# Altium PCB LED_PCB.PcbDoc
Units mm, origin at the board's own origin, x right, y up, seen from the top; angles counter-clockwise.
Board outline 99.87 x 66.87 mm, 2 copper layers (Top Layer, Bottom Layer); 110 components, 90 nets, 363 pads, 120 vias.
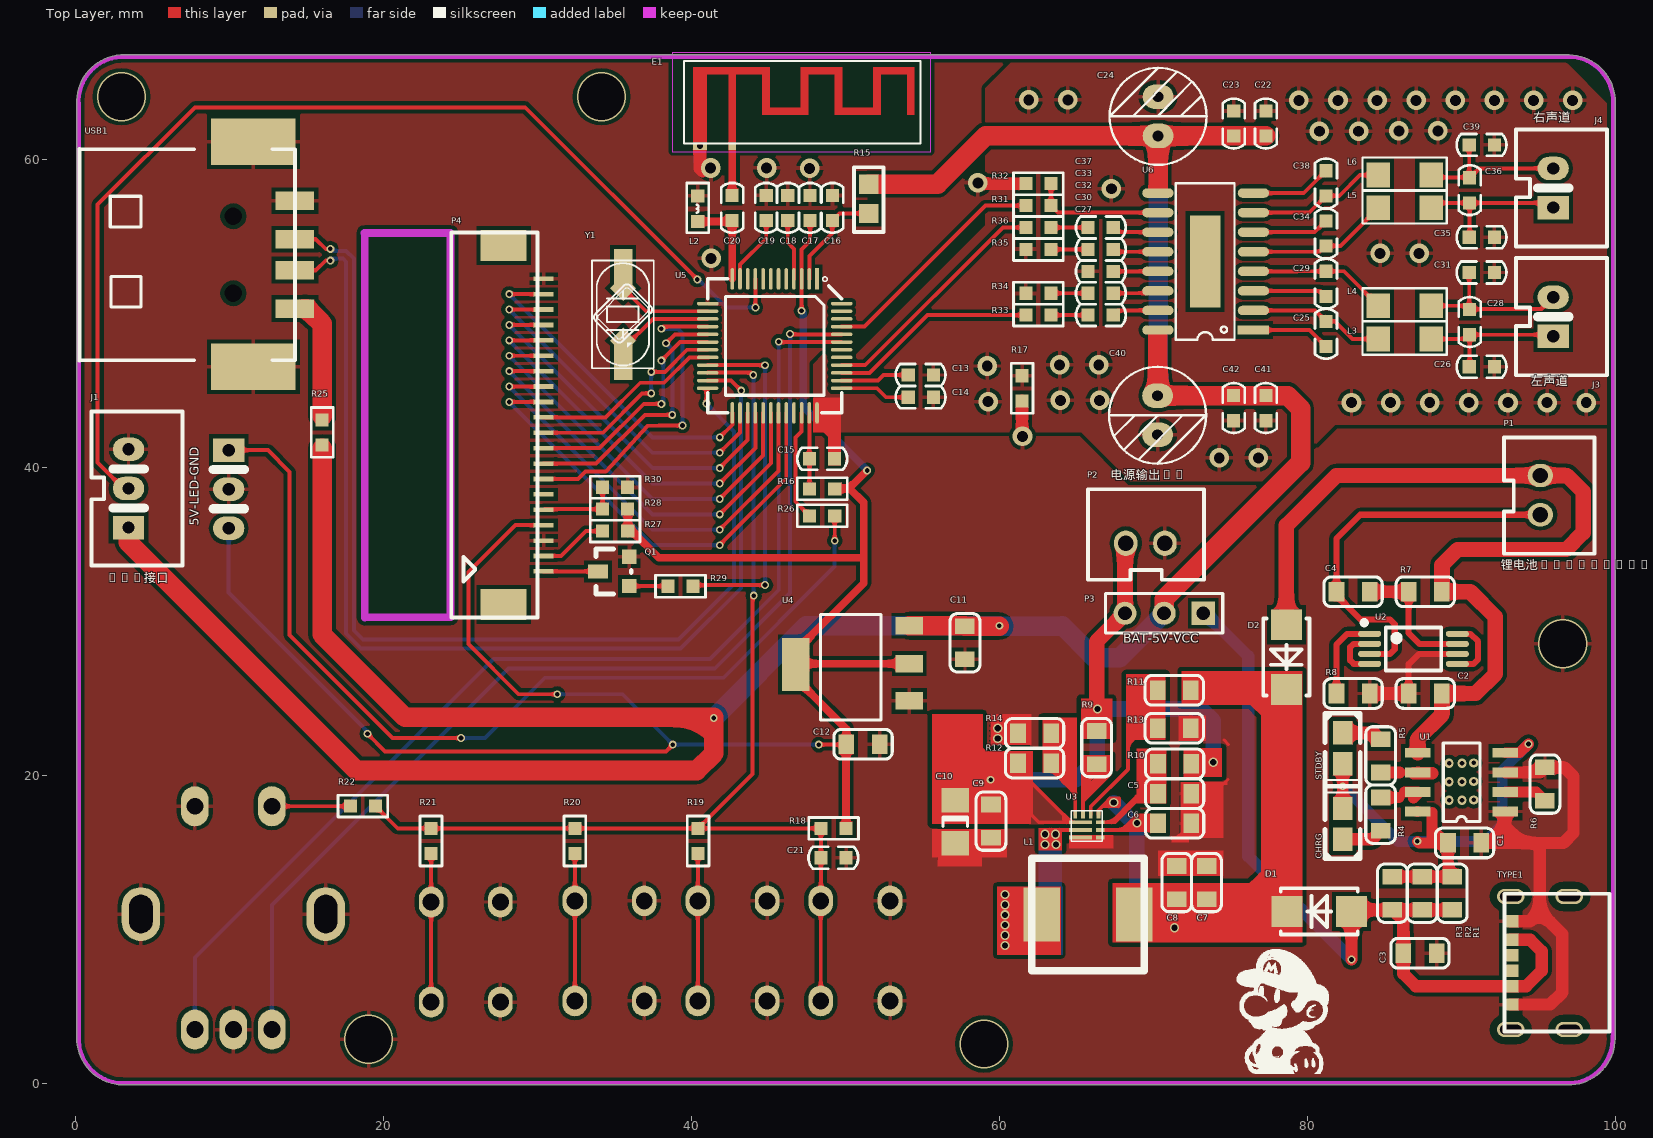
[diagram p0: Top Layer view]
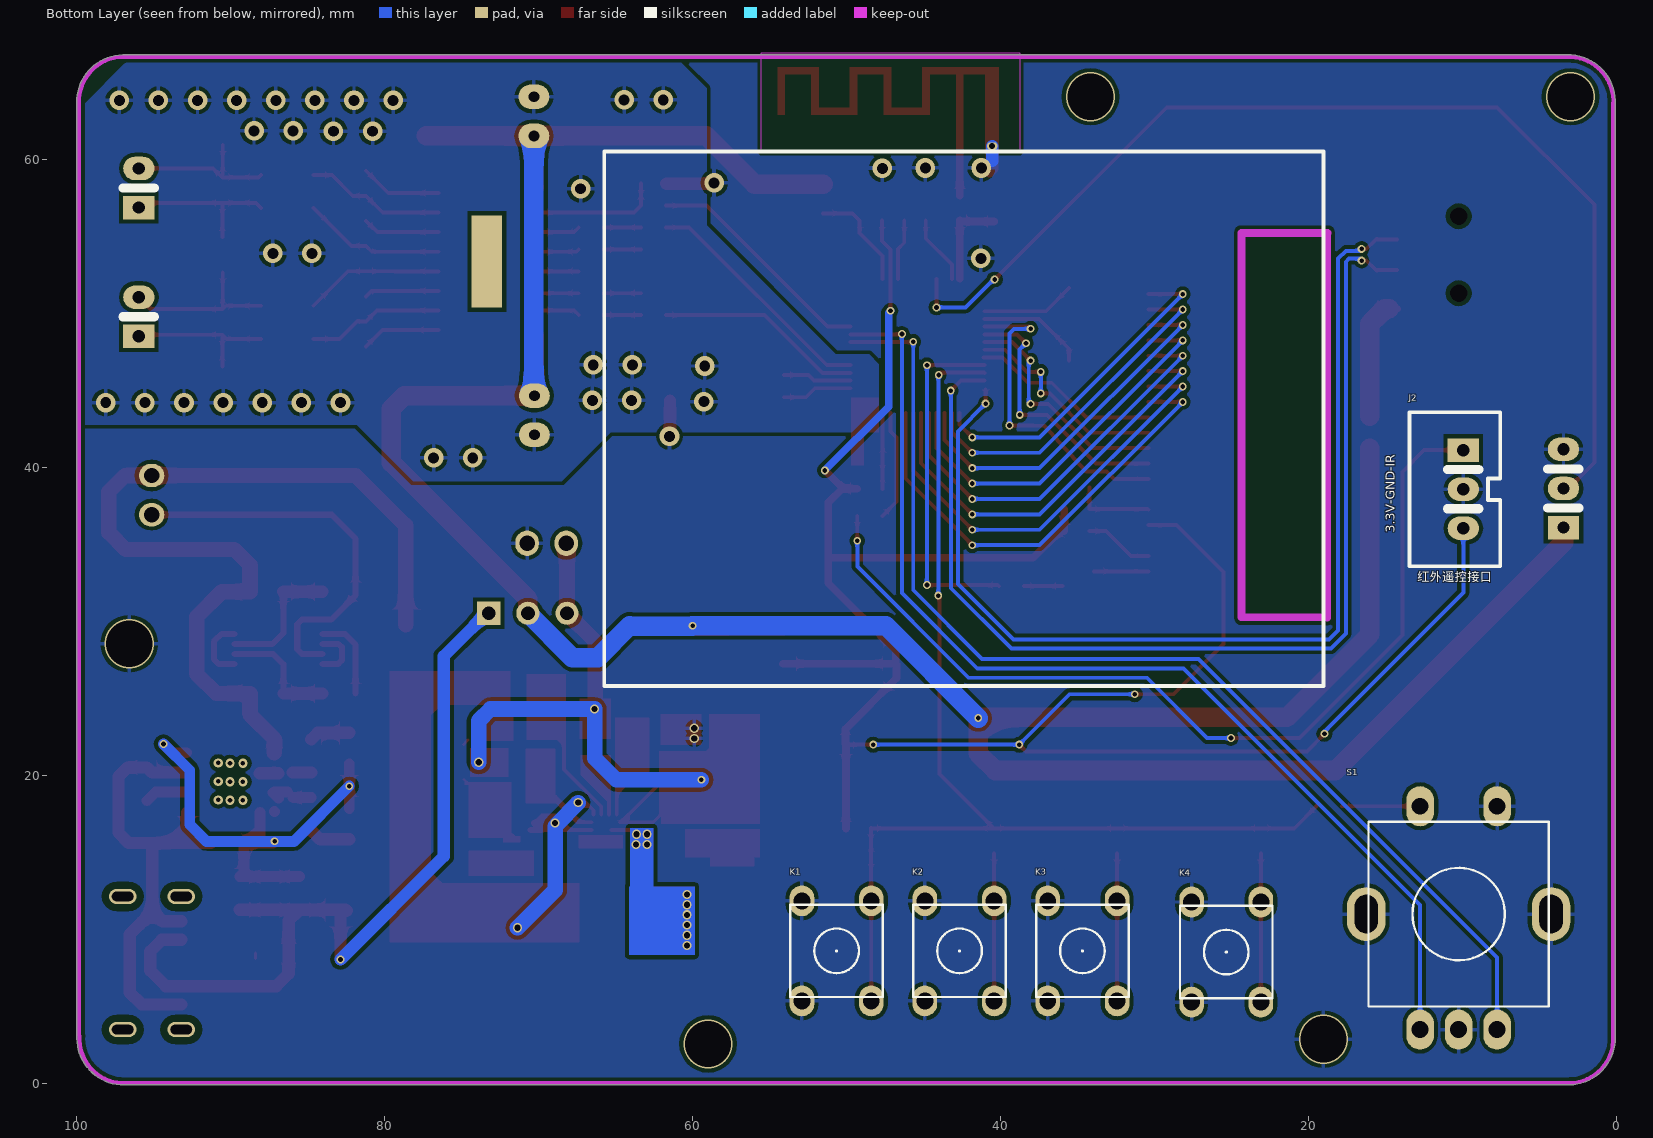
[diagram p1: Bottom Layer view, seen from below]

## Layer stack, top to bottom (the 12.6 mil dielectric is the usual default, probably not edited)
Top Solder: solder mask 0.0102, Solder Resist, Dk 3.5
Top Layer: signal copper 0.0356
Dielectric 1: dielectric 0.32, FR-4, Dk 4.8
Bottom Layer: signal copper 0.0356
Bottom Solder: solder mask 0.0102, Solder Resist, Dk 3.5

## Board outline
0.081,2.784 0.081,22.784 cw(c0.208,22.784) 0.081,22.784 0.081,63.598 cw(c3.104,63.779) 2.917,66.802 cw(c3.104,63.779) 2.918,66.802 2.917,66.802 cw(c2.926,66.675) 2.926,66.802 96.698,66.802 cw(c96.698,66.675) 96.718,66.801 cw(c96.737,66.675) 96.729,66.802 cw(c96.915,63.779) 99.938,63.965 cw(c99.811,63.957) 99.938,63.957 99.938,3.143 cw(c96.915,2.962) 99.943,2.962 cw(c96.915,2.962) 97.126,-0.059 cw(c97.104,0.066) 97.104,-0.061 3.286,-0.061 cw(c3.104,2.962) 0.081,2.776 cw(c0.208,2.784)

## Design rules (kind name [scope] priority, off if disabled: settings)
Clearance [All] p1: gap=0.254 ignorepadtopadclearanceinfootprint=TRUE
ComponentClearance [All] p1: gap=0 collisioncheckmode=3 verticalgap=0 showdistances=FALSE
DiffPairsRouting DiffPair_50omuDiffPairsRouting [InDifferentialPair ('USBDX')] p1: maxlimit=0.508 minlimit=0.254 mostfreqgap=0.254 toplayer_minwidth=0.152 toplayer_maxwidth=0.381 toplayer_prefwidth=0.254 bottomlayer_minwidth=0.152 bottomlayer_maxwidth=0.381 bottomlayer_prefwidth=0.254 maxuncoupledlength=12.7
HoleSize [All] p1: absolutevalues=TRUE maxlimit=10 minlimit=0 maxpercent=80.000 minpercent=20.000
HoleToHoleClearance [All] p1: gap=0 allowstackedmicrovias=TRUE
MatchedLengths MatchedLengths_1 [InDifferentialPair ('USBDX')] p1: tolerance=25.4 checknetsindiffpair=FALSE checkdiffpairvsdiffpair=TRUE checkxsignals=TRUE checkothers=TRUE
MatchedLengths DiffPair_50omuMatchedLengths [InDifferentialPair ('USBDX')] p2: tolerance=0.254 checknetsindiffpair=FALSE checkdiffpairvsdiffpair=TRUE checkxsignals=TRUE checkothers=TRUE
MatchedLengths [InDifferentialPair ('USBDX')] p3: tolerance=25.4 checknetsindiffpair=FALSE checkdiffpairvsdiffpair=TRUE checkxsignals=TRUE checkothers=TRUE
MinimumSolderMaskSliver [All] p1: minsoldermaskwidth=0
PolygonConnect [All] p1: connectstyle=Relief reliefconductorwidth=0.254 reliefentries=4 polygonreliefangle="90 Angle" airgapwidth=0.254
RoutingVias [All] p1: holewidth=0.711 width=1.27 viastyle="Through Hole" minholewidth=0.152 minwidth=0.254 maxholewidth=0.711 maxwidth=1.27
SilkToSilkClearance [All] p1: silktosilkclearance=0
SilkToSolderMaskClearance [IsPad] p1: minsilkscreentomaskgap=0 clearancetoexposedcopper=TRUE
SolderMaskExpansion [All] p1: expansion=0.102
Width [All] p1: maxlimit=2.54 minlimit=0.152 preferedwidth=0.254
23 further rules are at their usual default settings.

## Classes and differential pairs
component class LED原理图: C1 C2 C3 C4 C5 C6 C7 C8 C9 C10 C11 C12 CHRG D1 D2 L1 P1 P2 P3 R1 R2 R3 R4 R5 R6 R7 R8 R9 R10 R11 R12 R13 R14 STDBY TYPE1 U1 U2 U3 U4 U?
component class BLE主控原理图: C13 C14 C15 C16 C17 C18 C19 C20 C21 E1 J1 J2 K1 K2 K3 K4 L2 P4 Q1 R15 R16 R17 R18 R19 R20 R21 R22 R25 R26 R27 R28 R29 R30 S1 U5 USB1 Y1
component class 功放原理图: C22 C23 C24 C25 C26 C27 C28 C29 C30 C31 C32 C33 C34 C35 C36 C37 C38 C39 C40 C41 C42 J3 J4 L3 L4 L5 L6 R31 R32 R33 R34 R35 R36 U6
differential pair USBDX: +USBDX_P -USBDX_N

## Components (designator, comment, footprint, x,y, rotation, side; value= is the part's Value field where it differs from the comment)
C1 "Cap" 0805C 89.091,15.644 r0 top value=106
C2 "Cap" 0805C 88.699,25.347 r180 top value=106
C3 "Cap" 0805C 88.354,8.481 r180 top value=226
C4 "Cap" 0805C 81.852,31.951 r0 top value=106
C5 "Cap" 0805C 72.426,18.848 r180 top value=475
C6 "Cap" 0805C 70.269,16.918 r0 top value=105
C7 "Cap" 0805C 73.419,14.149 r270 top value=226
C8 "Cap" 0805C 71.488,14.149 r270 top value=226
C9 "Cap" 0805C 59.423,18.137 r270 top value=226
C10 "Cap2" C1206 57.112,17.019 r270 top value=100uF/10V
C11 "Cap" 0805C 57.734,27.559 r90 top value=105
C12 "Cap" 0805C 52.197,22.048 r180 top value=105
C13 "105" C0603 54.864,46.025 r0 top
C14 "105" C0603 54.864,44.577 r0 top
C15 "105" C0603 48.456,40.589 r180 top
C16 "105" C0603 49.124,56.866 r270 top
C17 "105" C0603 47.676,56.866 r270 top
C18 "105" C0603 46.228,56.866 r270 top
C19 "105" C0603 44.831,56.866 r270 top
C20 "2.7P" C0603 42.621,56.866 r270 top
C21 "NC/100pF" C0603 49.2,14.682 r0 top
C22 "104" C0603 77.272,62.357 r90 top
C23 "105" C0603 75.184,62.357 r90 top
C24 "220uF/25V" EC2.5-6.3 70.282,62.816 r90 top
C25 "105" C0603 81.174,48.692 r270 top
C26 "105" C0603 91.288,46.558 r0 top
C27 "225" C0603 66.546,49.911 r180 top
C28 "474" C0603 90.5,49.454 r270 top
C29 "105" C0603 81.174,51.943 r270 top
C30 "225" C0603 66.546,51.333 r180 top
C31 "105" C0603 91.288,52.68 r0 top
C32 "105" C0603 66.546,52.756 r180 top
C33 "225" C0603 66.546,54.178 r180 top
C34 "105" C0603 81.178,55.22 r90 top
C35 "105" C0603 91.288,54.966 r0 top
C36 "474" C0603 90.5,58.014 r270 top
C37 "225" C0603 66.546,55.601 r180 top
C38 "105" C0603 81.178,58.471 r90 top
C39 "105" C0603 91.288,60.96 r0 top
C40 "220uF/25V" EC2.5-6.3 70.231,43.411 r270 top
C41 "105" C0603 77.267,43.868 r270 top
C42 "104" C0603 75.179,43.868 r270 top
CHRG "RED" LED-0805 82.258,15.879 r90 top
D1 "SS34" LC-SMA(DO-214AC)_S2 80.734,11.199 r0 top
D2 "SS34" LC-SMA(DO-214AC)_S2 78.6,27.713 r90 top
E1 "BT_ANT" 新F天线 42.621,60.884 r0 top
J1 "LED" CON-3X2.54 3.429,38.659 r90 top
J2 "CON3" CON-3X2.54 9.931,38.608 r270 bottom
J3 "喇叭" CON-2X2.54 95.921,48.539 r90 top
J4 "喇叭" CON-2X2.54 95.921,56.896 r90 top
K1 "" KEY 50.622,8.636 r270 bottom
K2 "" KEY 42.641,8.636 r270 bottom
K3 "" KEY 34.661,8.636 r270 bottom
K4 "" KEY 25.324,8.56 r270 bottom
L1 "Inductor" 电感SMD 65.72,10.999 r180 top value=1R5
L2 "NC" L0603 40.386,56.818 r270 top
L3 "100R/10uH" R1206 86.284,48.362 r180 top
L4 "100R/10uH" R1206 86.284,50.521 r180 top
L5 "100R/10uH" R1206 86.284,56.871 r180 top
L6 "100R/10uH" R1206 86.284,59.004 r180 top
P1 "Header 2" XH2.54-2 95.092,39.498 r90 top
P2 "Header 2" XH2.54-2 68.174,35.103 r180 top
P3 "Header 3" HDR1X3 73.203,30.556 r180 top
P4 "串口彩屏" FFC-P20-1MM 29.083,42.774 r90 top
Q1 "S9014" SOT23 34.925,33.325 r90 top
R1 "Res2" 0805R 89.37,11.3 r90 top value=1R
R2 "Res2" 0805R 87.414,11.3 r90 top value=1R
R3 "Res2" 0805R 85.484,11.3 r90 top value=1R
R4 "Res2" 0805R 84.722,16.431 r90 top value=2K
R5 "Res2" 0805R 84.722,22.375 r270 top value=10K
R6 "Res2" 0805R 95.39,20.546 r270 top value=2K
R7 "Res2" 0805R 88.699,31.951 r180 top value=100R
R8 "Res2" 0805R 81.852,25.347 r0 top value=1K
R9 "Res2" 0805R 66.281,20.753 r90 top value=100K
R10 "Res2" 0805R 70.269,20.778 r0 top value=1K
R11 "Res2" 0805R 72.403,25.554 r180 top value=300K
R12 "Res2" 0805R 63.332,20.829 r180 top value=470K
R13 "Res2" 0805R 72.403,23.09 r180 top value=50K
R14 "Res2" 0805R 61.176,22.76 r0 top value="148K4      268K"
R15 "4R7" R0805 51.486,57.455 r270 top
R16 "4R7" R0603 48.463,38.633 r0 top
R17 "0R" R0603 61.443,45.161 r90 top
R18 "22K" R0603 49.2,16.586 r0 top
R19 "3K" R0603 40.411,15.773 r270 top
R20 "6.2K" R0603 32.41,15.773 r270 top
R21 "9.1K" R0603 23.063,15.773 r270 top
R22 "33K" R0603 18.646,18.034 r180 top
R25 "2R7" R0603 16.002,42.291 r90 top
R26 "1K" R0603 48.463,36.881 r0 top
R27 "0R" R0603 35.029,35.89 r180 top
R28 "3K" R0603 35.021,37.313 r0 top
R29 "10K" R0603 39.268,32.309 r180 top
R30 "10K" R0603 35.021,38.735 r0 top
R31 "10K" R0603 62.505,57.023 r180 top
R32 "10K" R0603 62.505,58.445 r180 top
R33 "1K" R0603 62.505,49.909 r180 top
R34 "1K" R0603 62.505,51.331 r180 top
R35 "1K" R0603 62.505,54.176 r180 top
R36 "1K" R0603 62.505,55.598 r180 top
S1 "编码器" BMQ+PUSH 10.236,11.024 r180 bottom
STDBY "GREEN" LED-0805 82.258,22.787 r270 top
TYPE1 "TYPE-CF-6P-RAT-L6.8W" TYPE-CF-6P-RAT-L6.8W 96.139,7.849 r90 top
U1 "TC4056A" SOP-8 92.824,17.682 r180 top
U2 "DW03D" LC-TSSOP-8_3x4.4x065P 86.855,28.242 r270 top
U3 "SY7065" QFN2*2-10 65.646,16.74 r0 top
U4 "AMS1117-3.3" SOT-233 54.111,24.868 r180 top
U5 "AC6951C" LQFP48 45.39,47.904 r270 top locked
U6 "CS8676" SOP16-EP 76.759,48.946 r180 top
USB1 "USB" USBSMT 10.236,56.331 r270 top
Y1 "HS-24M" JZ 35.535,49.962 r0 top locked

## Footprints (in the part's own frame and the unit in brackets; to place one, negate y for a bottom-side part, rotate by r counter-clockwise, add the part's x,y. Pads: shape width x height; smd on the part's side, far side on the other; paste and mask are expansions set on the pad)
0805C [mil]
  rect 40x50 smd: 1(0,0) 2(85,0)
  silkscreen extent -32,-38 117,38, body extent 3,-25 82,25, height 30
0805R [mil]
  rect 40x50 smd: 1(0,0) 2(85,0)
  silkscreen extent -32,-38 117,38, body extent 3,-25 82,25, height 30
BMQ+PUSH [mm]
  oval 1.8x2.6 hole 1.1: 1(-2.5,-7.5) 2(0,-7.5) 3(2.5,-7.5) 4(-2.5,7) 5(2.5,7)
  oval 2.5x3.5 hole 1.5 slot 2.5 at 90 deg: 6(-6,0) 7(6,0)
  silkscreen extent -5.85,-6 5.85,6
C0603 [mm]
  rect 0.85x0.85 smd: 1(-0.815,0) 2(0.815,0)
  silkscreen extent -1.63,-0.71 1.61,0.71
C1206 [mm] "Chip Capacitor; Body 3.2 x 1.6 mm (LxW typ)"
  rect 1.6x1.8 smd: 1(-1.4,0) 2(1.4,0)
  silkscreen extent -0.3,-0.8 0.3,0.8
CON-2X2.54 [mil]
  rect 60x80 hole 31.5: 1(0,0)
  oval 60x80 hole 31.5: 2(100,0)
  silkscreen extent -100,-138 200,94
CON-3X2.54 [mil]
  rect 60x80 hole 31.5: 1(-100,0)
  oval 60x80 hole 31.5: 2(0,0) 3(100,0)
  silkscreen extent -197,-138 197,94
EC2.5-6.3 [mm]
  oval 1.6x2 hole 0.7: 1(-1.27,0.01) 2(1.27,0.01)
  silkscreen extent -3.15,-3.14 3.15,3.16
FFC-P20-1MM [mm]
  rect 0.3x1.3 smd: 1(-9.5,-1.3) 2(-8.5,-1.3) 3(-7.5,-1.3) 4(-6.5,-1.3) 5(-5.5,-1.3) 6(-4.5,-1.3) 7(-3.5,-1.3) 8(-2.5,-1.3) 9(-1.5,-1.3) 10(-0.5,-1.3) 11(0.5,-1.3) 12(1.5,-1.3) 13(2.5,-1.3) 14(3.5,-1.3) 15(4.5,-1.3) 16(5.5,-1.3) 17(6.5,-1.3) 18(7.5,-1.3) 19(8.5,-1.3) 20(9.5,-1.3)
  rect 2x3 smd: 21(11.651,1.3) 22(-11.651,1.3)
  silkscreen extent -12.5,-0.9 12.5,4.7
HDR1X3 [mm] "Connector; Header; 3 Position"
  rect 1.5x1.5 hole 0.9: 1(0,0)
  round 1.5 hole 0.9: 2(2.54,0) 3(5.08,0)
  silkscreen extent -1.27,-1.27 6.35,1.27
JZ [mm]
  rect 1.2x2.5 smd: 1(0,-3) 2(0,3)
  rect 1.2x1.2 smd rot 45: 1(0,-1.7) 2(0,1.7)
  rect 1.2x1.2 on Top Overlay rot 45: 3(1.7,0) 4(-1.7,0)
  silkscreen extent -2.01,-3.5 1.99,3.5
KEY [mm]
  oval 2x1.6 hole 1.1: 1(-3.25,2.25) 1(3.25,2.25) 2(-3.25,-2.25) 2(3.25,-2.25)
  silkscreen extent -3,-3 3,3
L0603 [mm]
  rect 0.85x0.85 smd: 1(-0.83,0) 2(0.83,0)
  silkscreen extent -1.68,-0.71 1.56,0.71
LC-SMA(DO-214AC)_S2 [mm]
  rect 2x2 smd: 1(2.1,0) 2(-2.1,0)
  silkscreen extent -2.5,-1.5 2.5,1.5
LC-TSSOP-8_3x4.4x065P [mm]
  oval 0.4x1.5 smd mask+0.051: 1(-0.975,-2.85) 2(-0.325,-2.85) 3(0.325,-2.85) 4(0.975,-2.85) 5(0.975,2.85) 6(0.325,2.85) 7(-0.325,2.85) 8(-0.975,2.85)
  silkscreen extent -1.85,-3.35 1.4,1.8
LED-0805 [mil]
  rect 60x50 smd: 1(0,0) 2(78.74,0)
  silkscreen extent -50,-45 136,45
LQFP48 [mm]
  rect 1.4x0.23 smd: 1(-4.357,2.739)
  oval 1.4x0.23 smd: 2(-4.357,2.239) 3(-4.357,1.739) 4(-4.357,1.239) 5(-4.357,0.739) 6(-4.357,0.239) 7(-4.357,-0.261) 8(-4.357,-0.761) 9(-4.357,-1.261) 10(-4.357,-1.761) 11(-4.357,-2.261) 12(-4.357,-2.761) 25(4.343,-2.761) 26(4.343,-2.261) 27(4.343,-1.761) 28(4.343,-1.261) 29(4.343,-0.761) 30(4.343,-0.261) 31(4.343,0.239) 32(4.343,0.739) 33(4.343,1.239) 34(4.343,1.739) 35(4.343,2.239) 36(4.343,2.739)
  oval 0.23x1.4 smd: 13(-2.757,-4.361) 14(-2.257,-4.361) 15(-1.757,-4.361) 16(-1.257,-4.361) 17(-0.757,-4.361) 18(-0.257,-4.361) 19(0.243,-4.361) 20(0.743,-4.361) 21(1.243,-4.361) 22(1.743,-4.361) 23(2.243,-4.361) 24(2.743,-4.361) 37(2.743,4.339) 38(2.243,4.339) 39(1.743,4.339) 40(1.243,4.339) 41(0.743,4.339) 42(0.243,4.339) 43(-0.257,4.339) 44(-0.757,4.339) 45(-1.257,4.339) 46(-1.757,4.339) 47(-2.257,4.339) 48(-2.757,4.339)
  silkscreen extent -4.49,-4.36 4.34,4.34
QFN2*2-10 [mm]
  rect 1.5x0.25 smd: 1(-0.4,0.25) 2(-0.4,-0.25) 3(-0.4,-0.75)
  rect 0.55x0.25 smd mask+0.102: 4(0.875,-0.75)
  rect 0.55x0.25 smd: 5(0.875,-0.25) 6(0.875,0.25)
  rect 0.25x0.5 smd: 7(0.75,0.75) 8(0.25,0.75) 9(-0.25,0.75) 10(-0.75,0.75)
  silkscreen extent -1,-1 1,1, body extent -1.47,-1 1.01,1.01, height 63.5
R0603 [mm]
  rect 0.85x0.85 smd: 1(-0.815,0) 2(0.815,0)
  silkscreen extent -1.62,-0.71 1.62,0.71
R0805 [mm]
  rect 1.25x1.25 smd: 1(-0.96,0.007) 2(0.94,0.007)
  silkscreen extent -2.06,-0.95 2.16,0.96
R1206 [mm]
  rect 1.52x1.6 smd: 1(-1.71,0) 2(1.71,0)
  silkscreen extent -2.73,-1.14 2.74,1.02
SOP16-EP [mm]
  rect 2x6 all layers, no hole: 0(3.429,-4.445)
  rect 2.032x0.61 smd: 1(0.3,0)
  oval 2.032x0.61 smd: 2(0.3,-1.27) 3(0.3,-2.54) 4(0.3,-3.81) 5(0.3,-5.08) 6(0.3,-6.35) 7(0.3,-7.62) 8(0.3,-8.89) 9(6.5,-8.89) 10(6.5,-7.62) 11(6.5,-6.35) 12(6.5,-5.08) 13(6.5,-3.81) 14(6.5,-2.54) 15(6.5,-1.27) 16(6.5,0)
  silkscreen extent 1.52,-9.53 5.33,0.64
SOP-8 [mil]
  rect 65x25 smd: 1(0,0) 2(0,-50) 3(0,-100) 4(0,-150) 5(224.41,-150) 6(224.41,-100) 7(224.41,-50) 8(224.41,0)
  silkscreen extent 65,-175 159,25
SOT23 [mil]
  rect 36x36 smd: 1(-39.7,-40) 2(35.3,-40)
  rect 36x50 smd: 3(-2.2,40)
  silkscreen extent -60,-45 55,45
SOT-233 [mil]
  rect 70x45 smd: 1(0,0) 2(0,-95.04) 3(0,-192)
  rect 70x135 smd: 4(290.35,-92.95)
  silkscreen extent 72,-221 227,49
TYPE-CF-6P-RAT-L6.8W [mm]
  oval 1x1.8 hole 1.4 slot 0.6 at 0 deg unplated: 0(-4.32,-0.829) 0(-4.32,2.971) 0(4.32,-0.829) 0(4.32,2.971)
  rect 0.8x1 smd: 1(-2.7,2.971) 2(-1.5,2.971) 3(-0.5,2.971) 4(0.5,2.971) 5(1.5,2.971) 6(2.7,2.971)
  silkscreen extent -4.44,-3.43 4.49,3.37, body extent -4.44,-3.98 4.5,3.92, height 1.61
USBSMT [mm]
  rect 1.2x2.5 smd: 1(-1,4) 2(1.5,4) 3(3.5,4) 4(6,4)
  rect 3x5.5 smd: 5(-4.837,1.3) 6(9.773,1.3)
  round 0 hole 1.15: 7(5,0) 8(0,0)
  silkscreen extent -4.36,-10 9.36,4
XH2.54-2 [mil]
  oval 60x65 hole 39.37: 1(0,0) 2(-100.1,0)
  silkscreen extent -200,-138 97,93, body extent -198,-142 98,94, height 276
新F天线 [mm]
  rect 0.5x0.5 smd mask+0.003: 1(0,0)
  rect 0.5x0.5 on Top Solder mask+0.003: 1(0,0)
  rect 0.9x0.5 smd mask+0.003: 2(-2.1,0)
  oval 0.7x0.5 hole 0.4 mask+0.01: 2(-2.1,0)
  rect 0.9x0.5 on Top Solder: 2(-2.1,0)
  Top Layer region: 9.151,4.65 11.851,4.65 11.851,5.15 9.151,5.15
  Top Layer region: 6.651,2.01 9.651,2.01 9.651,2.51 6.651,2.51
  Top Layer region: 4.451,4.65 7.151,4.65 7.151,5.15 4.451,5.15
  Top Layer region: 4.451,2.01 4.951,2.01 4.951,5.15 4.451,5.15
  Top Layer region: 1.951,2.01 2.451,2.01 2.451,5.15 1.951,5.15
  Top Layer region: -0.247,-0.25 0.253,-0.25 0.253,5.15 -0.247,5.15
  Top Layer region: -2.549,-0.25 -1.65,-0.25 -1.65,5.15 -2.549,5.15
  Top Layer region: -2.549,4.65 2.451,4.65 2.451,5.15 -2.549,5.15
  Top Layer region: 1.951,2.01 4.951,2.01 4.951,2.51 1.951,2.51
  Top Layer region: 6.651,2.01 7.151,2.01 7.151,5.15 6.651,5.15
  Top Layer region: 9.151,2.01 9.651,2.01 9.651,5.15 9.151,5.15
  Top Layer region: 11.351,2.01 11.851,2.01 11.851,5.15 11.351,5.15
  silkscreen extent -3.13,0.18 12.22,5.53
电感SMD [mm]
  rect 2.35x3.5 smd: 1(-3,0) 2(3,0)
  silkscreen extent -3.65,-3.65 3.65,3.65

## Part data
C1 C2 C3 C4 C5 C6 C7 C8 C9 C10 C11 C12: "Capacitor"
C13 C14 C15 C16 C17 C18 C19 C20 C21 C22 C23 C25 C26 C27 C28 C29 C30 C31 C32 C33 C34 C35 C36 C37 C38 C39 C41 C42: library part CAP-0603
C24 C40: library part +CAP
CHRG STDBY: library part LED0, "Typical INFRARED GaAs LED"
D1 D2: library part Diode, "Default Diode"
J1: library part CON3, "Connector"
J2: "Connector"
J3 J4: library part CON2, "Connector"
K1 K2 K3 K4: library part Key
L2 L3 L4 L5 L6: library part L
P1 P2: "Header, 2-Pin"
P3: "Header, 3-Pin"
P4: library part LCD-20P
Q1: library part NPN
R1 R2 R3 R4 R5 R6 R7 R8 R9 R10 R11 R12 R13 R14: "Resistor"
R15 R17 R18 R19 R20 R21 R22 R26 R27 R28 R29 R30 R31 R32 R33 R34 R35 R36: library part RES-0603
R16 R25: library part RES
S1: library part CON7, "Connector"
Y1: library part CRYSTAL

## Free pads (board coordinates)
  rect 2.35x4 on Top Solder: 0(89.98,19.587)
  rect 2.35x4 on Bottom Solder: 1(89.903,19.562)

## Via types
v1: diameter 0.508, hole 0.305, Top Layer to Bottom Layer, 47 vias
v2: diameter 1.27, hole 0.711, Top Layer to Bottom Layer, 38 vias
v3: diameter 0.6, hole 0.4, Top Layer to Bottom Layer, 17 vias
v4: diameter 0.6, hole 0.3, Top Layer to Bottom Layer, 8 vias
v5: diameter 3.2, hole 3, Top Layer to Bottom Layer, 5 vias
v6: diameter 0.5, hole 0.3, Top Layer to Bottom Layer, 4 vias
v7: diameter 0.6/0.6 (per signal layer), hole 0.3, Top Layer to Bottom Layer, 1 vias

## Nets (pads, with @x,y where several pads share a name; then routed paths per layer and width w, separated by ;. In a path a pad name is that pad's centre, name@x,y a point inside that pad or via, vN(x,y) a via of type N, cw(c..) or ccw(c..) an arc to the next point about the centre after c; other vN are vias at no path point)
5V: C11.2 C22.1 C23.1 C24.1 C40.1 C41.1 C42.1 J1.1 P3.2 R15.1 R25.1 U4.3 U6.9 U6.16 | length 207
  Top Layer w0.254: C40.1 70.243,44.683 C40.1@70.259,44.698 ; U6.9 70.259,58.217 ; C22.1@77.267,61.546 C22.1
  Top Layer w1.27: J1.1 3.429,35.154 18.237,20.345 40.31,20.345 41.427,21.463 41.427,22.787 ; R25.1@16.002,41.274 16.002,29.185 21.387,23.8 40.335,23.8 ; R15.1 55.951,58.415 59.083,61.546 C24.1 ; U4.3 57.708,29.745 C11.2 v1@59.969,29.718 ; C40.1@70.243,44.683 C41.1 78.685,44.683 79.527,43.84 79.527,40.335 70.663,31.471 P3.2 ; C40.1@70.259,44.698 70.259,48.565 ; 70.259,58.217 70.272,58.23 C24.1 ; C22.1@77.267,61.546 C24.1 ; 40.335,23.8 41.427,23.8 v1(41.427,23.749) 41.427,22.787 ; 40.335,23.8 41.348,22.787 41.427,22.787
  Bottom Layer w1.27: v1(41.427,23.749) 47.422,29.743 v1(59.969,29.743) v1@59.995,29.743 ; v1@59.995,29.718 64.031,29.718 64.058,29.745 66.142,27.661 67.767,27.661 P3.2 ; C40.1 70.272,44.711 C24.1
+3.3V: C12.2 C17.2 J2.3 P4.4 R16.2 R18.2 R27.1 R28.2 U4.2 U4.4 U5.3 | length 146.9
  Top Layer w0.254: v1(18.948,22.733) 20.091,21.59 38.329,21.59 v1(38.764,22.025) ; P4.4 28.552,36.274 25.502,33.223 25.502,28.55 28.753,25.298 v1(31.267,25.298) ; v1(47.117,50.19) 47.129,50.202 U5.3 47.129,54.164 47.676,54.712 C17.2 ; v1(48.238,22.025) C12.2@50.015,22.025
  Top Layer w0.5: R28.2 35.844,37.305 R27.1 36.119,35.89 37.846,34.163 51.13,34.163 51.156,34.188 ; R16.2 50.19,38.633 ; R18.2 50.015,22.025 C12.2 50.038,23.038 46.736,26.34 U4.4 U4.4@46.789,27.282 ; v1(51.384,39.827) 50.19,38.633 ; U4.2 U4.4@46.789,27.282 ; U4.4@46.789,27.282 46.789,28.145 51.156,32.512 51.156,34.188 ; 50.19,38.633 50.267,38.633 51.156,37.744 51.156,34.188
  Bottom Layer w0.254: J2.3 9.931,31.902 18.948,22.885 v1(18.948,22.733) ; v1(31.267,25.298) 35.491,25.298 v1(38.764,22.025) v1(48.238,22.025)
  Bottom Layer w0.5: v1(47.117,50.19) 47.244,50.063 47.244,43.967 v1(51.384,39.827)
/CS: P4.7 U5.16 | length 21.2
  Top Layer w0.254: P4.7 32.619,39.274 33.096,39.751 34.414,39.751 37.11,42.705 37.978,42.745 ; 37.873,42.74 39.387,42.74 v1(39.395,42.748) ; v1(38.024,49.022) 38.164,49.162 U5.16
  Bottom Layer w0.254: v1(38.024,49.022) 39.091,49.022 39.395,48.717 v1(39.395,42.748)
/RSTB: P4.8 U5.17 | length 17.4
  Top Layer w0.254: P4.8 33.792,40.274 36.953,43.435 v1(38.735,43.435) ; v1(38.329,48.082) 38.908,48.662 U5.17
  Bottom Layer w0.254: v1(38.329,48.082) 38.735,47.676 v1(38.735,43.435)
AD_KEY: C21.1 K1.1 R18.1 R19.1 R20.1 R21.1 R22.1 U5.22 | length 75.2
  Top Layer w0.254: R22.1 20.906,16.588 R21.1 R20.1 R19.1 ; U5.22 41.044,46.177 43.84,46.177 v1(43.993,46.025) ; v1(44.018,31.699) 43.942,31.699 43.942,20.119 R19.1 ; K1.1@48.372,5.386 48.372,12.204 K1.1@48.385,12.217 ; K1.1@48.372,11.886 48.385,11.899 K1.1@48.385,12.217 ; R18.1@48.385,16.612 R18.1 ; R19.1 40.414,16.586 R18.1 ; K1.1@48.385,12.217 C21.1 R18.1
  Bottom Layer w0.254: v1(43.993,46.025) 43.993,46.05 44.018,46.076 v1(44.018,31.699)
AGND: C13.2 C14.2 C15.1 C22.2 C23.2 C24.2 C26.2 C31.2 C32.2 C35.2 C39.2 C40.2 C41.2 C42.2 R17.2 R34.2 R35.2 U5.36 | length 0.6
  Top Layer w0.254: 48.539,42.545 48.539,42.494 48.895,42.139 ; 49.271,42.794 49.301,42.824
  other v2: 74.244,40.64 76.784,40.64 82.829,44.235 85.369,44.235 87.909,44.235 90.449,44.235 92.989,44.235 95.529,44.235 98.069,44.235 59.233,44.298 63.932,44.374 66.472,44.374 59.182,46.609 63.881,46.685 66.421,46.685 84.684,53.924 87.224,53.924 67.234,58.115 80.747,61.849 83.287,61.849 85.903,61.874 88.443,61.874 79.411,63.856 81.951,63.856 84.491,63.856 87.031,63.856 89.571,63.856 92.111,63.856 94.651,63.856 97.191,63.856 61.874,63.881 64.414,63.881
BAT+: C2.1 D2.1 P1.1 R7.1 U1.5 | length 58.3
  Top Layer w1: D2.1 78.6,36.257 81.841,39.498 P1.1 96.822,39.498 97.866,38.454 97.866,35.787 96.774,34.695 89.713,34.695 88.699,33.682 R7.1 90.538,31.951 92.164,30.325 92.164,26.617 90.894,25.347 C2.1 88.699,23.965 87.124,22.39 U1.5
BL_A: P4.2 R27.2 | length 4.5
  Top Layer w0.254: P4.2 31.505,34.274 33.122,35.89 R27.2
BL_K: P4.1 Q1.3 | length 3.5
  Top Layer w0.254: P4.1 Q1.3@33.904,33.274
BL_LIGHT: R29.1 U5.21 | length 22.7
  Top Layer w0.254: R29.1 40.16,32.385 v1(44.755,32.385) ; U5.21 v1(44.757,46.662)
  Bottom Layer w0.254: v1(44.755,32.385) 44.755,32.61 44.757,32.612 v1(44.757,46.662)
BT_ANT: C20.1 E1.1@42.621,60.884 | length 3.2
  Top Layer w0.254: E1.1@42.621,60.858 E1.1@42.647,60.884
  Top Layer w0.5: C20.1 E1.1@42.621,60.858
BT_RF: C20.2 L2.2 U5.12 | length 6.1
  Top Layer w0.254: C20.2@42.558,55.988 C20.2 ; U5.12@42.621,52.269 U5.12
  Top Layer w0.5: L2.2 C20.2@42.558,55.988 ; U5.12@42.621,52.269 C20.2
BTAVDD: C19.2 U5.11 | length 4.5
  Top Layer w0.254: U5.11 43.129,53.187 44.831,54.889 C19.2
CTRL: R31.1 R32.1 U6.10 | length 8.6
  Top Layer w0.254: R32.1 R31.1 63.777,56.566 U6.10
DACL: R33.2 U5.39 | length 13.5
  Top Layer w0.254: U5.39 51.547,46.162 55.293,49.909 R33.2
DACR: R36.2 U5.40 | length 15.7
  Top Layer w0.254: U5.40 51.259,46.662 60.196,55.598 R36.2
DACVDD: C13.1 U5.38 | length 4.5
  Top Layer w0.254: U5.38 52.088,45.662 52.451,46.025 C13.1
DB0: P4.19 U5.25 | length 21.7
  Top Layer w0.254: v1(28.143,51.274) P4.19 ; v1(41.808,41.976) 42.629,42.796 U5.25
  Bottom Layer w0.254: v1(28.143,51.274) 37.441,41.976 v1(41.808,41.976)
DB1: P4.18 U5.26 | length 22.9
  Top Layer w0.254: v1(28.143,50.274) P4.18 ; v1(41.808,40.976) 43.129,42.296 U5.26
  Bottom Layer w0.254: v1(28.143,50.274) 37.441,40.976 v1(41.808,40.976)
DB2: P4.17 U5.27 | length 24.1
  Top Layer w0.254: v1(28.143,49.274) P4.17 ; v1(41.808,39.976) 43.629,41.796 U5.27
  Bottom Layer w0.254: v1(28.143,49.274) 37.441,39.976 v1(41.808,39.976)
DB3: P4.16 U5.28 | length 25.3
  Top Layer w0.254: v1(28.143,48.274) P4.16 ; v1(41.808,38.976) 44.129,41.296 U5.28
  Bottom Layer w0.254: v1(28.143,48.274) 37.441,38.976 v1(41.808,38.976)
DB4: P4.15 U5.29 | length 26.5
  Top Layer w0.254: v1(28.143,47.274) P4.15 ; v1(41.808,37.976) 44.629,40.796 U5.29
  Bottom Layer w0.254: v1(28.143,47.274) 37.441,37.976 v1(41.808,37.976)
DB5: P4.14 U5.30 | length 27.7
  Top Layer w0.254: v1(28.143,46.274) P4.14 ; v1(41.808,36.976) 45.129,40.296 U5.30
  Bottom Layer w0.254: v1(28.143,46.274) 37.441,36.976 v1(41.808,36.976)
DB6: P4.13 U5.31 | length 28.9
  Top Layer w0.254: v1(28.143,45.274) P4.13 ; v1(41.808,35.976) 45.629,39.796 U5.31
  Bottom Layer w0.254: v1(28.143,45.274) 37.441,35.976 v1(41.808,35.976)
DB7: P4.12 U5.32 | length 30.1
  Top Layer w0.254: v1(28.143,44.274) P4.12 ; v1(41.808,34.976) 46.129,39.296 U5.32
  Bottom Layer w0.254: v1(28.143,44.274) 37.441,34.976 v1(41.808,34.976)
GND: C1.2 C2.2 C3.1 C5.1 C6.2 C7.1 C8.1 C9.2 C10.2 C11.1 C12.1 C16.1 C17.1 C18.1 C19.1 C21.2 E1.2@40.521,60.884 J1.3 J2.2 K1.2 K2.2 K3.2 K4.2 L2.1 P2.2 P4.3 P4.20 Q1.2 R6.1 R8.2 R13.1 R14.1 R17.1 R30.2 R32.2 S1.2 S1.5 S1.6 S1.7 TYPE1.1 TYPE1.6 U1.1 U1.3 U2.6 U3.3 U3.4 U4.1 U5.13 USB1.1 USB1.5 USB1.6 | length 54.3
  Top Layer w0.2: 71.514,16.029 71.819,16.308 ; 74.511,19.483 74.816,19.762 ; 74.562,22.328 74.841,22.023 ; C3.1@88.354,8.151 C3.1
  Top Layer w0.4: C2.2 86.54,27.241 87.216,27.917 U2.6
  Top Layer w0.8: E1.2@40.521,60.884 40.521,59.431 v2@40.694,59.258 ; v2(58.572,58.496) 58.623,58.445 R32.2 ; R17.1 61.443,42.062 v2(61.468,42.037) ; R8.2 86.515,25.347 85.753,25.347 ; C1.2 91.783,15.644 ; 92.774,16.609 U1.1@92.774,17.606 ; U1.3 95.066,20.222 R6.1 96.657,20.546 97.244,19.959 97.244,16.304 96.584,15.644 94.793,15.644 ; TYPE1.1 95.725,5.149 96.52,5.944 96.52,9.71 95.047,11.184 ; TYPE1.6 94.412,10.549 95.047,11.184 ; 91.783,15.644 92.824,16.685 ; 91.783,15.644 92.901,15.644 ; 92.824,16.685 92.824,15.72 92.901,15.644 ; 92.824,16.685 93.866,15.644 ; 92.901,15.644 93.866,15.644 ; 93.866,15.644 94.793,15.644 ; 94.793,15.644 95.047,15.39 95.047,11.184
  Bottom Layer w0.8: 40.499,59.919 40.521,59.941 E1.2@40.521,60.884
  other v2: 41.25,53.594 47.648,59.436 41.225,59.461 44.856,59.461
  other v3: 59.861,22.429 59.861,23.09
  other v5: 19.012,2.896 96.545,28.575
HPVDD: C15.2 R16.1 U5.35 | length 4.9
  Top Layer w0.254: U5.35 47.629,40.602 C15.2 47.641,38.641 R16.1
IRDA: R26.1 U5.34 | length 7.2
  Top Layer w0.254: U5.34 47.129,42.353 46.736,41.961 46.736,37.793 R26.1
LED: J1.2 U5.9 | length 72
  Top Layer w0.254: J1.2 3.099,38.659 1.422,40.335 1.422,57.085 7.736,63.398 29.185,63.398 v1(40.361,52.222) ; v1(44.129,50.41) U5.9
  Bottom Layer w0.254: v1(40.361,52.222) 40.437,52.222 42.249,50.41 v1(44.129,50.41)
MUTE: R31.2 U5.45 | length 15.2
  Top Layer w0.254: U5.45 51.219,49.162 59.08,57.023 R31.2
NetC1_1: C1.1 CHRG.2 R1.2 R2.2 R3.2 STDBY.2 U1.4 U1.8 | length 35.4
  Top Layer w0.7: CHRG.2 v6(82.258,19.333) STDBY.2 ; R3.2 R2.2 R1.2 89.091,13.739 C1.1 C1.1@88.913,15.644 ; v6(87.109,15.745) 87.211,15.644 C1.1@88.913,15.644 ; U1.8@87.109,17.667 U1.8 ; 88.049,15.695 88.049,17.616 ; 88.064,17.631 88.064,16.492 C1.1@88.913,15.644 ; C1.1@88.964,15.593 C1.1@88.913,15.644 ; U1.4 93.745,21.492 v6(94.323,22.07)
  Bottom Layer w0.7: v6(82.258,19.333) 85.846,15.745 v6(87.109,15.745) 91.529,15.745 92.621,16.838 92.621,20.368 v6(94.323,22.07)
NetC4_1: C4.1 P1.2 U2.3 | length 25.5
  Top Layer w0.4: U2.3 85.337,27.917 85.636,28.217 85.636,29.842 85.331,30.147 83.426,30.147 81.852,31.722 C4.1 81.852,35.408 83.4,36.956 P1.2
NetC4_2: C4.2 R7.2 U2.7 | length 8.7
  Top Layer w0.4: R7.2 86.54,29.269 87.242,28.567 U2.7
  Top Layer w0.8: C4.2 R7.2
NetC5_2: C5.2 R10.1 U3.6 | length 7.1
  Top Layer w0.25: U3.6 67.243,16.99 ; 66.993,16.986 67.239,16.986 ; 67.467,16.986 67.463,16.99 ; 69.202,18.721 68.974,18.492 ; 69.38,19.061 69.314,19.061 68.745,18.492 ; 67.239,16.986 67.243,16.99 ; 67.239,16.986 67.459,16.986 67.463,16.99 ; 67.243,16.99 68.745,18.492 ; 67.243,16.99 67.463,16.99 ; 67.463,16.99 68.34,17.867 68.348,17.867 68.974,18.492 ; 68.745,18.492 68.974,18.492
NetC6_1: C6.1 C7.2 C8.2 D1.2 D2.2 L1.1 R11.1 U3.5 U3.7 | length 68.7
  Top Layer w0.25: U3.7 66.396,17.769 66.711,18.084 ; U3.5 66.525,16.486 67.958,16.486 ; v3(67.399,18.264) 67.348,18.213 66.84,18.213 ; 68.593,16.689 v3@68.771,16.689 ; v3@68.961,16.879 68.898,16.816 v3@68.771,16.689 ; v3@69.05,16.791 69.253,16.994 69.253,17.07 ; C6.1@69.837,16.486 69.431,16.486 ; C6.1 C6.1@70.091,17.095 ; 66.711,18.084 66.84,18.213 ; 66.711,18.084 66.76,18.035 67.018,18.035 ; 66.84,18.213 67.145,18.518 67.729,18.518 67.755,18.492 67.755,18.086 67.704,18.035 67.399,18.035 67.018,18.035 ; 66.84,18.213 67.018,18.035 ; 67.958,16.486 68.898,17.426 69.202,17.426 ; 67.958,16.486 68.263,16.486 ; 68.263,16.486 69.05,17.273 ; 68.263,16.486 69.179,16.486 ; v3@68.771,16.689 69.142,16.689 69.244,16.791 69.523,17.07 ; 69.05,17.273 69.253,17.07 ; 69.05,17.273 69.202,17.426 ; 69.05,17.273 69.726,17.273 ; 69.179,16.486 69.329,16.587 69.431,16.486 ; 69.179,16.486 69.431,16.486 ; 69.202,17.426 69.761,17.426 C6.1@69.914,17.273 ; 69.253,17.07 69.523,17.07 ; 69.523,17.07 70.066,17.07 C6.1@70.091,17.095 ; 69.523,17.07 69.726,17.273 ; 69.726,17.273 C6.1@69.914,17.273 ; C6.1@69.914,17.273 C6.1@70.091,17.095
  Top Layer w0.4: C6.1 C6.1@70.142,16.791 ; C6.1@70.498,16.486 69.837,16.486 C6.1@70.142,16.791 ; v3(71.336,10.136) 71.514,10.314 71.514,10.39 ; C8.2 C7.2 ; v3@69.05,16.791 68.898,16.791 68.898,16.816 v3(68.898,16.943) 68.961,16.879 v3@69.05,16.791 ; v3@69.05,16.791 69.244,16.791 C6.1@70.142,16.791
  Top Layer w0.5: 78.6,15.356 78.642,15.314 78.727,15.229
  Top Layer w0.8: 71.946,10.06 72.377,10.491 D1.2@78.169,10.491 ; R11.1 78.6,25.554 78.6,15.898 ; 76.238,12.189 76.238,12.52 77.102,13.383 ; 76.543,24.889 77.356,24.077 77.356,22.984 ; 78.169,15.491 78.6,15.461 ; D1.2@78.6,10.898 78.6,15.229 ; 78.727,15.229 78.642,15.229 78.6,15.229 ; 78.6,15.229 78.6,15.356 78.6,15.413 ; 78.6,15.229 78.431,15.229 78.6,15.413 ; 78.6,15.413 78.6,15.461 ; 78.6,15.413 78.642,15.458 ; 78.6,15.461 78.6,15.465 ; 78.6,15.461 78.642,15.458 ; 78.6,15.465 78.642,15.458 ; 78.6,15.465 78.228,15.525 78.6,15.898 ; 78.6,15.465 78.6,15.898
  Top Layer w2: D1.2@78.642,11.275 78.642,15.229 78.642,15.314 78.642,15.458
  Bottom Layer w0.5: v3@68.898,16.714 v3(68.898,16.943)
  Bottom Layer w1.016: v3(67.399,18.264) 68.783,16.833 68.898,16.714 68.898,12.574 v3(71.336,10.136)
NetC25_1: C25.1 L3.2 U6.2 | length 8.9
  Top Layer w0.254: U6.2 80.465,50.216 C25.1 81.76,49.507 82.906,48.362 L3.2
NetC25_2: C25.2 U6.1 | length 5.2
  Top Layer w0.254: U6.1 80.105,48.946 C25.2
NetC26_1: C26.1 C28.2 J3.1 L3.1 | length 10.2
  Top Layer w0.254: L3.1 90.223,48.362 C28.2 ; C26.1 90.5,46.586 C28.2 ; J3.1 95.821,48.639 C28.2
NetC27_1: C27.1 U6.15 | length 3
  Top Layer w0.254: C27.1 67.666,50.216 U6.15
NetC27_2: C27.2 R33.1 | length 2.4
  Top Layer w0.254: R33.1 C27.2@65.728,49.909
NetC28_1: C28.1 C31.1 J3.2 L4.1 | length 10.7
  Top Layer w0.254: L4.1 90.248,50.521 C28.1@90.473,50.296 ; C31.1 C28.1@90.473,50.296 ; J3.2 95.138,50.296 C28.1@90.473,50.296
NetC29_1: C29.1 L4.2 U6.4 | length 9
  Top Layer w0.254: U6.4 79.299,52.756 79.301,52.758 C29.1 82.336,52.758 L4.2
NetC29_2: C29.2 U6.3 | length 4.9
  Top Layer w0.254: U6.3 80.816,51.486 C29.2
NetC30_1: C30.1 U6.14 | length 3
  Top Layer w0.254: C30.1 70.106,51.333 U6.14
NetC30_2: C30.2 R34.1 | length 2.4
  Top Layer w0.254: R34.1 65.728,51.331 C30.2
NetC32_1: C32.1 U6.13 | length 2.9
  Top Layer w0.254: C32.1 U6.13
NetC33_1: C33.1 U6.12 | length 3
  Top Layer w0.254: C33.1 67.513,54.026 U6.12
NetC33_2: C33.2 R35.1 | length 2.4
  Top Layer w0.254: R35.1 C33.2@65.728,54.176
NetC34_1: C34.1 L5.2 U6.5 | length 9.3
  Top Layer w0.254: U6.5 80.8,54.026 C34.1 82.108,54.405 L5.2
NetC34_2: C34.2 U6.6 | length 5
  Top Layer w0.254: U6.6 80.44,55.296 C34.2
NetC35_1: C35.1 C36.2 J4.1 L5.1 | length 10.4
  Top Layer w0.254: L5.1 88.322,57.199 C36.2 ; C35.1 90.5,54.993 C36.2 ; J4.1 95.618,57.199 C36.2
NetC36_1: C36.1 C39.1 J4.2 L6.1 | length 10.3
  Top Layer w0.254: L6.1 88.142,58.856 90.473,58.856 C39.1 ; C36.1 91.108,59.436 J4.2
NetC37_1: C37.1 U6.11 | length 3
  Top Layer w0.254: C37.1 67.666,55.296 U6.11
NetC37_2: C37.2 R36.1 | length 2.4
  Top Layer w0.254: R36.1 C37.2@65.728,55.598
NetC38_1: C38.1 L6.2 U6.7 | length 9.1
  Top Layer w0.254: U6.7 80.088,56.566 C38.1 82.035,57.656 83.384,59.004 L6.2
NetC38_2: C38.2 U6.8 | length 5.3
  Top Layer w0.254: U6.8 79.728,57.836 C38.2
NetCHRG_1: CHRG.1 R4.1 | length 2.7
  Top Layer w0.8: CHRG.1 83.064,15.879 83.071,15.872 84.163,15.872 R4.1
NetJ2_1: J2.1 R26.2 | length 61.2
  Top Layer w0.254: J2.1 12.471,41.148 13.894,39.726 13.894,29.134 20.574,22.454 v1(25.019,22.454) ; v1(49.278,35.257) R26.2
  Bottom Layer w0.254: v1(25.019,22.454) 26.568,22.454 30.48,26.365 42.062,26.365 49.276,33.579 49.276,35.255 v1(49.278,35.257)
NetK2_1: K2.1 R19.2 | length 9.6
  Top Layer w0.254: K2.1@40.39,5.387 40.39,11.887 40.39,14.937 R19.2
NetK3_1: K3.1 R20.2 | length 9.6
  Top Layer w0.254: K3.1@32.41,5.386 32.41,11.886 R20.2
NetK4_1: K4.1 R21.2 | length 9.7
  Top Layer w0.254: R21.2 23.073,14.948 23.073,11.81 K4.1@23.073,5.31
NetL1_2: L1.2 U3.2 | length 2.4
  Top Layer w0.25: v3@62.856,16.49 63.614,16.49 U3.2
  other v3: 60.338,8.993 60.338,9.653 60.338,10.314 60.338,10.974 60.338,11.634 60.338,12.295 62.929,15.546 63.64,15.546 62.929,16.206 63.614,16.206
NetQ1_1: Q1.1 R29.2 | length 2.5
  Top Layer w0.254: Q1.1 38.446,32.316 R29.2
NetR4_2: R4.2 U1.7 | length 2.6
  Top Layer w0.7: R4.2 85.916,18.59 ; 86.277,18.952 U1.7 ; 86.855,18.539 87.196,18.88 U1.7@87.217,18.901
NetR5_1: R5.1 STDBY.1 | length 2.6
  Top Layer w0.8: STDBY.1 84.31,22.787 R5.1
NetR5_2: R5.2 U1.6 | length 3.8
  Top Layer w0.245: 85.814,20.089 85.941,20.216 85.947,20.222 ; U1.6@86.887,20.171 88.064,20.171
  Top Layer w0.8: R5.2 85.687,20.216 85.941,20.216 ; U1.6@86.881,20.165 87.124,20.165 88.064,20.165 ; U1.6@87.124,20.216 U1.6@87.16,20.216
NetR6_2: R6.2 U1.2 | length 2.8
  Top Layer w0.7: U1.2 94.825,18.952 R6.2
NetR8_1: R8.1 U2.1 | length 5.6
  Top Layer w0.4: R8.1 81.852,28.522 82.547,29.217 U2.1
NetR9_1: R9.1 U3.9 | length 16
  Top Layer w0.25: U3.9 65.396,18.391 ; 66.104,20.143 65.396,19.436 ; R9.1@66.434,20.728 65.621,19.915 ; 67.12,20.067 65.443,18.391 65.396,18.391 ; 65.396,18.391 65.396,18.674 ; 65.396,18.674 66.878,20.156 66.891,20.169 66.815,20.169 65.545,18.899 65.396,18.899 ; 65.396,18.674 65.396,18.899 ; 65.396,18.899 65.396,18.979 ; 65.396,18.979 66.586,20.169 66.26,20.169 65.396,19.305 ; 65.396,18.979 65.396,19.305 ; 65.396,19.305 65.396,19.436 ; 65.396,19.436 65.396,19.69 ; 65.396,19.69 65.396,20.478 65.469,20.55 65.621,20.397 65.621,19.915 ; 65.396,19.69 65.621,19.915
NetR11_2: R11.2 R13.2 U3.8 | length 7
  Top Layer w0.25: U3.8 65.896,18.006 68.313,20.423 68.313,22.048 ; 68.517,22.506 68.313,22.302 ; 68.745,22.48 68.567,22.302 ; 68.313,22.048 68.313,22.302 ; 68.313,22.048 68.567,22.302 ; 68.313,22.302 68.567,22.302
NetR12_1: R12.1 R14.2 U3.10 | length 12.9
  Top Layer w0.25: 64.503,19.458 64.478,19.483 ; 64.859,20.651 64.896,20.614 64.896,18.861 ; U3.10 64.896,18.861 ; 63.792,19.966 R12.1@63.792,20.369 ; 63.792,19.966 63.332,20.425 R12.1 R12.1@63.792,20.369 ; 63.792,19.966 64.072,19.686 ; 63.792,19.966 63.919,20.093 63.919,20.242 R12.1@63.792,20.369 ; 64.072,19.686 64.072,20.042 64.275,20.245 64.275,19.686 64.478,19.483 ; 64.072,19.686 64.656,19.102 ; 64.478,19.483 64.478,20.321 64.656,20.143 64.656,19.102 ; 64.656,19.102 64.896,18.861
  Top Layer w0.4: R12.1 63.335,20.832 R14.2
NetR22_2: R22.2 S1.4 | length 5.1
  Top Layer w0.254: S1.4 R22.2@17.821,18.024
NetR25_2: R25.2 USB1.4 | length 8.2
  Top Layer w0.5: USB1.4 USB1.4@14.744,50.331
  Top Layer w1.27: USB1.4@14.744,50.331 15.021,50.331 16.002,49.35 R25.2@16.002,43.358
NetU2_2: U2.2 U2.4 | length 3.6
  Top Layer w0.4: U2.4 82.979,27.267 82.741,27.506 82.741,28.344 82.964,28.567 U2.2
NetU2_5: U2.5 U2.8 | length 4.2
  Top Layer w0.4: U2.5 90.757,27.267 91.046,27.556 91.046,28.725 90.554,29.217 U2.8
NetU5_14: U5.14 Y1.2 | length 6.1
  Top Layer w0.254: Y1.2@35.535,51.662 37.035,50.162 U5.14
NetU5_15: U5.15 Y1.1 | length 7.1
  Top Layer w0.254: Y1.1@35.535,46.962 35.535,47.727 37.47,49.662 U5.15
RDB: P4.11 U5.20 | length 12.3
  Top Layer w0.254: P4.11 34.409,43.274 36.653,45.518 38.203,45.518 39.847,47.162 U5.20 U5.20@41.085,47.162
RS: P4.9 U5.18 | length 15.3
  Top Layer w0.254: P4.9 34.009,41.274 36.881,44.145 v1(38.024,44.145) ; v1(38.024,46.959) 39.227,48.162 U5.18
  Bottom Layer w0.254: v1@37.948,46.959 38.147,46.759 38.147,44.269 v1(38.024,44.145)
RTCVDD: C18.2 U5.4 | length 4
  Top Layer w0.254: C18.2 46.228,54.61 46.629,54.209 U5.4
S1: S1.1 U5.44 | length 70.3
  Top Layer w0.254: v1(46.38,48.692) 46.41,48.662 U5.44
  Bottom Layer w0.254: S1.1 12.736,11.618 28.092,26.975 41.491,26.975 46.38,31.864 v1(46.38,48.692)
S2: S1.3 U5.43 | length 72.7
  Top Layer w0.254: v1(45.644,48.184) 45.72,48.108 45.774,48.162 U5.43
  Bottom Layer w0.254: S1.3 7.736,8.193 27.127,27.584 41.173,27.584 45.644,32.055 v1(45.644,48.184)
USBDX_N: U5.23 USB1.3 | length 70.9
  Top Layer w0.254: USB1.3 15.613,52.831 16.232,53.45 v1(16.535,53.45) ; U5.23 42.552,45.662 v1(43.205,45.009) v1@43.332,45.009
  Bottom Layer w0.254: v1(16.535,53.45) 16.662,53.577 17.348,53.577 17.551,53.374 17.551,29.228 18.509,28.27 39.276,28.27 43.209,32.204 43.205,32.207 v1(43.205,45.009)
USBDX_P: U5.24 USB1.2 | length 68.3
  Top Layer w0.254: USB1.2 15.613,54.831 16.232,54.212 v1(16.535,54.212) ; v1(40.945,44.163) U5.24@40.945,45.078
  Bottom Layer w0.254: v1(16.535,54.212) 16.662,54.085 17.559,54.085 18.059,53.584 18.059,29.439 18.644,28.854 39.141,28.854 42.748,32.461 42.748,42.36 v1(40.945,44.163)
VCC: C3.2 D1.1 P3.1 R1.1 R2.1 R3.1 TYPE1.2 TYPE1.5 | length 54.4
  Top Layer w0.8: D1.1@82.428,11.25 82.478,11.3 R3.1 ; v1(82.834,8.082) D1.1 ; R3.1@85.458,11.275 R3.1 ; R1.1 R2.1 R3.1 ; TYPE1.5 94.436,9.349 95.174,8.611 95.174,7.343 94.179,6.349 TYPE1.2 86.996,6.349 86.195,7.15 C3.2 86.195,10.589 R3.1
  Bottom Layer w0.8: P3.1 73.33,30.556 76.124,27.762 76.124,14.783 82.829,8.077 v1(82.834,8.082)
VCOM: C14.1 U5.37 | length 4.6
  Top Layer w0.254: U5.37 52.019,45.162 52.603,44.577 C14.1
VDDIO: P4.5 R28.1 R30.1 | length 5.3
  Top Layer w0.254: P4.5 30.422,37.313 R28.1 R30.1
VMCU: C16.2 R15.2 U5.2 | length 7
  Top Layer w0.254: U5.2 47.629,53.75 49.124,55.245 C16.2 49.588,56.515 R15.2
VOUT: C9.1 C10.1 P2.1 P3.3 R9.2 R10.2 R12.2 U3.1 | length 46.7
  Top Layer w0.2: 58.776,21.845 59.055,21.54
  Top Layer w0.25: 61.709,18.645 61.709,17.807 62.526,16.99 64.355,16.99 ; 61.811,19.585 62.027,19.585 64.148,17.463 ; U3.1@64.685,16.99 U3.1@64.634,16.99 ; v3@73.724,21.058 73.851,20.931 v3(73.851,20.88) ; 64.148,17.463 64.148,17.197 64.355,16.99 ; 64.148,17.463 64.161,17.463 U3.1@64.634,16.99 ; 64.355,16.99 U3.1@64.634,16.99
  Top Layer w0.4: R9.2@65.926,22.887 66.281,23.242 66.332,23.293 v3(66.332,24.334)
  Top Layer w0.5: P2.1@68.123,35.052 P2.1
  Top Layer w1.016: v6(59.398,19.737) 59.423,19.712 C9.1 ; R9.2 66.281,23.242 66.281,28.715 P3.3 P2.1@68.123,35.052
  Bottom Layer w1.016: v6(59.398,19.737) 64.91,19.737 66.332,21.159 v3(66.332,24.334) 73.089,24.334 73.851,23.572 v3(73.851,20.88)
WRB: P4.10 U5.19 | length 13.7
  Top Layer w0.254: P4.10 34.222,42.274 36.779,44.831 v1(37.363,44.831) ; v1(37.363,46.228) 38.252,46.228 39.686,47.662 U5.19
  Bottom Layer w0.254: v1(37.363,44.831) v1(37.363,46.228)
pads on no net: E1.1@42.621,60.884 E1.2@40.521,60.884 P4.6 P4.21 P4.22 TYPE1.0 TYPE1.3 TYPE1.4 U5.1 U5.5 U5.6 U5.7 U5.8 U5.10 U5.33 U5.41 U5.42 U5.46 U5.47 U5.48 U6.0 USB1.7 USB1.8 Y1.3 Y1.4
copper on no net:
  other v4: 90.005,18.419 90.767,18.438 89.167,19.619 90.005,19.619 90.767,19.638 89.167,20.819 90.005,20.819 90.767,20.838
  other v5: 58.967,2.591 2.972,64.086 34.138,64.086
  other v7: 89.167,18.419

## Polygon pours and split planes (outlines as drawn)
GND on Top Layer "Top Layer-GND 3" (solid, remove dead copper, pour order 21): 0.081,2.784 0.081,22.784 cw(c0.208,22.784) 0.081,22.784 0.081,63.598 cw(c3.104,63.779) 2.917,66.802 cw(c3.104,63.779) 2.918,66.802 2.917,66.802 cw(c2.926,66.675) 2.926,66.802 96.698,66.802 cw(c96.698,66.675) 96.718,66.801 cw(c96.737,66.675) 96.729,66.802 cw(c96.915,63.779) 99.938,63.965 cw(c99.811,63.957) 99.938,63.957 99.938,3.143 cw(c96.915,2.962) 99.943,2.962 cw(c96.915,2.962) 97.126,-0.059 cw(c97.104,0.066) 97.104,-0.061 3.286,-0.061 cw(c3.104,2.962) 0.081,2.776 cw(c0.208,2.784)
AGND on Top Layer "Top Layer-AGND" (solid, pour order 18): 47.879,42.291 65.278,42.291 68.453,39.116 78.105,39.116 81.788,42.799 99.568,42.799 99.568,63.5 96.267,66.801 61.213,66.801 59.055,64.643 59.055,55.753 50.673,47.371 48.514,47.371 47.879,46.736
no net on Top Layer "Top Layer-No Net" (solid, pour order 10): 74.257,19.585
GND on Top Layer "Top Layer-GND 1" (solid, pour order 0): 71.92,19.483 71.946,19.458 74.511,19.458 74.511,13.489 59.398,13.489 59.398,8.409 55.588,8.409 55.588,16.537 62.192,16.537 62.192,14.886 71.717,14.886 71.717,19.483 74.511,19.483 74.511,19.458
GND on Top Layer "Top Layer-GND" (solid, pour order 8): 71.59,23.903 71.59,22.252 74.765,22.252 74.765,19.585 74.511,19.585 74.511,19.584 74.511,13.489 75.146,13.489 75.146,23.903
VOUT on Top Layer "Top Layer-VOUT" (solid, pour order 12): 64.402,17.222 62.04,19.585 61.913,19.458 61.913,16.867 64.402,16.867
no net on Top Layer "Top Layer-No Net 1" (solid, pour order 14): 62.014,16.867
GND on Top Layer "Top Layer-GND 2" (solid, pour order 2): 64.478,16.156 64.478,14.886 71.717,14.886 71.717,16.156
GND on Bottom Layer "Bottom Layer-GND" (solid, remove dead copper, pour order 22): 0.081,2.784 0.081,22.784 cw(c0.208,22.784) 0.081,22.784 0.081,63.598 cw(c3.104,63.779) 2.917,66.802 cw(c3.104,63.779) 2.918,66.802 2.917,66.802 cw(c2.926,66.675) 2.926,66.802 96.698,66.802 cw(c96.698,66.675) 96.718,66.801 cw(c96.737,66.675) 96.729,66.802 cw(c96.915,63.779) 99.938,63.965 cw(c99.811,63.957) 99.938,63.957 99.938,3.143 cw(c96.915,2.962) 99.943,2.962 cw(c96.915,2.962) 97.126,-0.059 cw(c97.104,0.066) 97.104,-0.061 3.286,-0.061 cw(c3.104,2.962) 0.081,2.776 cw(c0.208,2.784)
AGND on Bottom Layer "Bottom Layer-AGND" (solid, pour order 16): 47.879,42.291 65.278,42.291 68.453,39.116 78.105,39.116 81.788,42.799 99.568,42.799 99.568,63.5 96.267,66.801 61.213,66.801 59.055,64.643 59.055,55.753 50.673,47.371 48.514,47.371 47.879,46.736
no net on Bottom Layer "Bottom Layer-No Net 1" (solid, pour order 4): 71.463,22.506
no net on Bottom Layer "Bottom Layer-No Net" (solid, pour order 6): 71.463,23.953

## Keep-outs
Keep-Out Layer:
  rectangle: 38.735,60.528 55.499,66.929
  region: 39.294,66.726
  lines w0.254: 0.203,2.743 0.203,63.602 cw(c3.099,63.779) 2.921,66.675 96.693,66.675 ; 0.203,2.769 ccw(c3.099,2.946) 3.277,0.051 97.049,0.051 ccw(c96.871,2.946) 99.766,3.124 ; 96.723,66.675 cw(c96.901,63.779) 99.797,63.957 99.797,3.124
  lines w0.5: 18.75,55.241 24.338,55.241 24.338,30.298 18.801,30.298 18.775,30.273 18.775,55.215

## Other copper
Top Layer:
  rectangle net AGND: 48.844,40.132 49.682,42.316
  rectangle net AGND: 47.879,42.291 49.682,44.565
  rectangle net GND: 71.59,22.252 73.368,23.903
  rectangle net GND: 74.384,19.407 74.765,19.585
  rectangle net GND: 71.869,22.429 72.934,23.75
  rectangle net GND: 71.717,15.978 74.511,19.585
  rectangle net GND: 71.133,15.673 72.276,16.079
  rectangle net GND: 70.269,13.489 74.511,15.165
  rectangle net GND: 70.676,13.59 74.308,14.682
  rectangle net GND: 64.478,15.292 67.374,16.156
  rectangle net GND: 64.478,15.648 66.993,16.156
  rectangle net GND: 59.398,21.998 62.065,24.03
  rectangle net GND: 55.588,14.682 60.465,16.537
  rectangle net GND: 55.944,14.098 58.839,14.886
  rectangle net NetC5_2: 68.872,18.213 70.828,21.769
  rectangle net NetC6_1: 67.297,9.171 74.308,13.057
  rectangle net NetL1_2: 62.522,15.165 64.046,16.613
  rectangle net NetL1_2: 59.83,8.383 63.97,12.828
  rectangle net NetR9_1: 65.265,20.067 67.247,21.337
  rectangle net NetR11_2: 68.186,22.328 70.768,26.62
  rectangle net NetR12_1: 62.776,20.194 65.011,23.801
  rectangle net VOUT: 55.588,21.54 58.89,24.03
  rectangle net VOUT: 55.588,17.426 62.141,21.617
  rectangle net VOUT: 65.265,22.379 67.297,25.02
  rectangle net VOUT: 71.92,19.94 74.435,21.82
  region net NetC6_1: 76.949,26.798 76.949,9.171 79.642,9.171 79.642,26.798
  region net NetC6_1: 74.155,13.057 74.155,9.171 77.051,9.171 77.051,13.057
  rectangle net NetC6_1: 71.793,24.614 77.102,26.798
  region net VOUT: 55.588,17.527 55.588,16.867 62.014,16.867 62.014,17.527
Bottom Layer:
  rectangle net NetL1_2: 62.522,8.358 64.046,16.613
  rectangle net NetL1_2: 59.83,8.358 64.097,12.828

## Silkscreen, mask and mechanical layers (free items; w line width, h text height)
Top Overlay:
  drawing of 1083 lines, arcs and shapes, not listed
  text "右声道" at 94.615,62.281 h1
  text "左声道" at 94.463,45.161 h1
  text "电源输出5V" at 67.208,39.065 h1
  text "5V-LED-GND" at 8.179,36.246 h1 r90
  text "锂电池3.7V~4.2V" at 92.507,33.223 h1
  text "LED接口" at 1.981,32.36 h1
  text "BAT-5V-VCC" at 68.021,28.448 h1
Bottom Overlay:
  lines w0.254: 65.596,25.826 19.003,25.826 19.003,60.526 65.703,60.526 65.703,25.826
  text "3.3V-GND-IR" at 14.173,35.789 h1 r270
  text "红外遥控接口" at 12.929,32.436 h1
Mechanical 1:
  lines w0.254: 96.698,66.675 2.926,66.675 ccw(c3.104,63.779) 0.208,63.602 ; 96.737,66.675 cw(c96.915,63.779) 99.811,63.957 99.811,3.124 ; 97.093,0.066 ccw(c96.915,2.962) 99.811,3.139 ; 97.104,0.066 3.282,0.066 cw(c3.104,2.962) 0.208,2.784 0.208,63.602 ; 0.208,63.602 0.208,63.602 ; 18.601,30.24 24.201,30.24 24.201,55.24 18.601,55.24 18.601,30.24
